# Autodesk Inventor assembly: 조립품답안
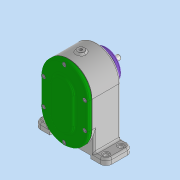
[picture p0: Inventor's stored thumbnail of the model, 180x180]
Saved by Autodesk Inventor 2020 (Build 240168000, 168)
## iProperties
Created: 2021-05
Part Number: 조립품답안
Document SubType Name: Assembly
Designer: Owner
Author: Owner
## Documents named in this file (18)
- C:\Users\Owner\Desktop\710507V1003\조립품답안.iam
- C:\Users\Owner\Desktop\710507V1003\본체.ipt
- C:\Users\Owner\Desktop\710507V1003\축 A.ipt
- C:\Users\Owner\Desktop\710507V1003\베어링 6001.ipt
- 베어링 6001.ipt
- C:\Users\Owner\Desktop\710507V1003\베어링 6002.ipt
- 베어링 6002.ipt
- C:\Users\Owner\Desktop\710507V1003\칼라.ipt
- C:\Users\Owner\Desktop\710507V1003\키 5 x 5 x 12.ipt
- C:\Users\Owner\Desktop\710507V1003\스퍼기어 A.ipt
- C:\Users\Owner\Desktop\710507V1003\축 B.ipt
- C:\Users\Owner\Desktop\710507V1003\키 4 x 4 x 12.ipt
- C:\Users\Owner\Desktop\710507V1003\스퍼기어 B.ipt
- C:\Users\Owner\Desktop\710507V1003\개스킷 A.ipt
- C:\Users\Owner\Desktop\710507V1003\개스킷 B.ipt
- C:\Users\Owner\Desktop\710507V1003\커버 A.ipt
- C:\Users\Owner\Desktop\710507V1003\커버 B.ipt
- C:\Users\Owner\Desktop\710507V1003\볼트 M4.ipt
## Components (2 placed, 2 different names)
1. 개스킷 A:1
2. 개스킷 B:1
